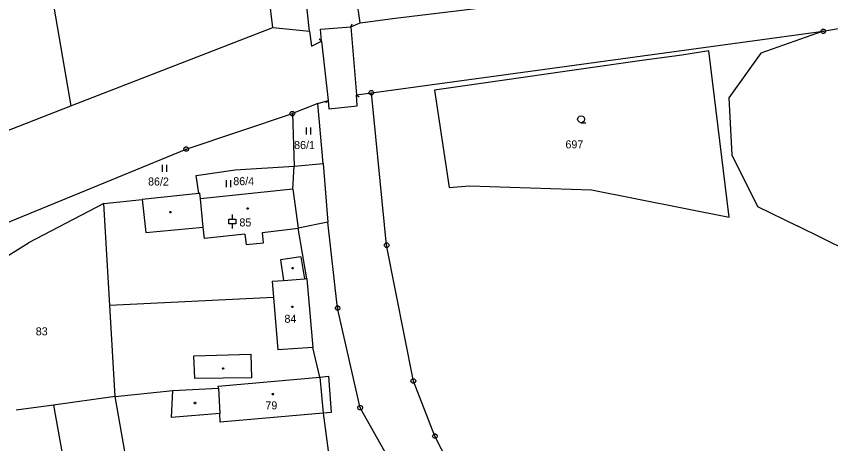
# Model space of a CAD drawing. Extents: x -812394 to -807601, y -1013098 to -1009266.
# Drawn here: x -809780.5 to -809607.5, y -1010903.9 to -1010813 of the extents above; entities that cross this region are included whole.
import ezdxf

# ---------------------------------------------------------------- set-up
doc = ezdxf.new("R2010")
doc.units = 0
for name, color, linetype in [('KN_HRANICE', 7, 'Continuous'), ('KN_KULTURY', 7, 'Continuous'), ('KN_MEZNIKY', 7, 'Continuous'), ('KN_PARCELY', 7, 'Continuous'), ('KN_SLUCKY', 7, 'Continuous')]:
    doc.layers.add(name, color=color, linetype=linetype)

# ---------------------------------------------------------------- blocks, each defined once
blk = doc.blocks.new('304')
blk.add_lwpolyline([(0, 0), (-0.38, 0.1), (-0.65, 0.37), (-0.75, 0.74), (-0.65, 1.11), (-0.38, 1.38), (-0.01, 1.48), (0.36, 1.38), (0.63, 1.11), (0.73, 0.73), (0.63, 0.35), (0.36, 0.08), (-0.02, -0.02), (0.98, -0.02)])
blk = doc.blocks.new('306')
for p, q in [((-0.5, 1.5), (-0.5, 0)), ((0.5, 0), (0.5, 1.5))]:
    blk.add_line(p, q)
blk = doc.blocks.new('318')
blk.add_line((0, 2), (0, 3))
blk.add_lwpolyline([(0, 0), (0, 1), (-0.75, 1), (-0.75, 2), (0, 2), (0.75, 2), (0.75, 1), (0, 1)])
blk = doc.blocks.new('402')
blk.add_lwpolyline([(0.09, 0.15), (0.18, 0), (0.09, -0.15), (-0.09, -0.15), (-0.18, 0), (-0.09, 0.15), (0.09, 0.15)])
blk = doc.blocks.new('105')
blk.add_line((-0.12, 0), (0.12, 0))
blk.add_lwpolyline([(0.15, 0.48), (0.4, 0.3), (0.5, 0.01), (0.4, -0.28), (0.15, -0.46), (-0.16, -0.46), (-0.41, -0.28), (-0.51, 0.01), (-0.41, 0.3), (-0.16, 0.48), (0.15, 0.48)])
blk = doc.blocks.new('4201')
blk.add_line((0, 0), (-0.5, -0.5))

msp = doc.modelspace()

# ---------------------------------------------------------------- linework, layer by layer
at = {"layer": 'KN_HRANICE'}
for p, q in [((-809776.12, -1010790.59), (-809768.91, -1010832.11)), ((-809718.25, -1010816.21), (-809720.85, -1010791.69)), ((-809707.49, -1010814.44), (-809710.32, -1010793.53)), ((-809726.02, -1010815.44), (-809727.35, -1010804.19)), ((-809700.6, -1010813.52), (-809643.49, -1010806.47)), ((-809609.07, -1010816.23), (-809583.77, -1010811.56)), ((-809709.48, -1010815.3), (-809707.49, -1010814.44)), ((-809707.49, -1010814.44), (-809701.59, -1010813.65)), ((-809701.59, -1010813.65), (-809700.6, -1010813.52)), ((-809768.91, -1010832.11), (-809726.02, -1010815.44)), ((-809726.02, -1010815.44), (-809718.25, -1010816.21)), ((-809718.25, -1010816.21), (-809717.84, -1010819.37)), ((-809715.88, -1010815.78), (-809709.48, -1010815.3)), ((-809715.65, -1010818.36), (-809715.88, -1010815.78)), ((-809705.08, -1010829.3), (-809609.07, -1010816.23)), ((-809717.84, -1010819.37), (-809715.65, -1010818.36)), ((-809708.23, -1010829.73), (-809705.08, -1010829.3)), ((-809708.1, -1010832.05), (-809708.23, -1010829.73)), ((-809701.84, -1010861.69), (-809705.08, -1010829.3)), ((-809795, -1010842.25), (-809768.91, -1010832.11)), ((-809716.45, -1010831.55), (-809721.87, -1010833.74)), ((-809716.45, -1010831.55), (-809714.29, -1010830.95)), ((-809715.34, -1010844.3), (-809716.45, -1010831.55)), ((-809714.29, -1010830.95), (-809714.1, -1010832.7)), ((-809714.1, -1010832.7), (-809708.1, -1010832.05)), ((-809744.44, -1010841.28), (-809721.87, -1010833.74)), ((-809721.87, -1010833.74), (-809721.48, -1010844.89)), ((-809788.59, -1010859.35), (-809744.44, -1010841.28)), ((-809721.48, -1010844.89), (-809715.34, -1010844.3)), ((-809715.34, -1010844.3), (-809714.35, -1010856.77)), ((-809742.28, -1010846.91), (-809734.04, -1010845.7)), ((-809734.04, -1010845.7), (-809721.48, -1010844.89)), ((-809721.76, -1010849.8), (-809721.48, -1010844.89)), ((-809741.74, -1010850.68), (-809742.28, -1010846.91)), ((-809741.74, -1010850.68), (-809753.76, -1010851.95)), ((-809741.55, -1010850.66), (-809741.74, -1010850.68)), ((-809741.42, -1010851.87), (-809741.55, -1010850.66)), ((-809721.76, -1010849.8), (-809741.42, -1010851.87)), ((-809761.95, -1010852.82), (-809777.96, -1010861.22)), ((-809761.95, -1010852.82), (-809753.76, -1010851.95)), ((-809760.65, -1010874.53), (-809761.95, -1010852.82)), ((-809714.35, -1010856.77), (-809720.67, -1010858.1)), ((-809718.78, -1010868.81), (-809720.67, -1010858.1)), ((-809712.26, -1010875.07), (-809714.35, -1010856.77)), ((-809791.19, -1010869.46), (-809777.96, -1010861.22)), ((-809696.17, -1010890.56), (-809701.84, -1010861.69)), ((-809726.19, -1010869.35), (-809723.78, -1010869.17)), ((-809726.19, -1010869.35), (-809725.89, -1010872.83)), ((-809723.78, -1010869.17), (-809719.27, -1010868.85)), ((-809718.78, -1010868.81), (-809719.27, -1010868.85)), ((-809718.78, -1010868.81), (-809717.54, -1010883.42)), ((-809725.89, -1010872.83), (-809760.65, -1010874.53)), ((-809759.51, -1010893.83), (-809760.65, -1010874.53)), ((-809707.45, -1010896.24), (-809712.26, -1010875.07)), ((-809716.06, -1010889.76), (-809717.54, -1010883.42)), ((-809737.62, -1010891.67), (-809716.06, -1010889.76)), ((-809716.06, -1010889.76), (-809714.21, -1010889.51)), ((-809714.21, -1010889.51), (-809713.65, -1010897.28)), ((-809691.58, -1010902.27), (-809696.17, -1010890.56)), ((-809759.51, -1010893.83), (-809747.26, -1010892.56)), ((-809747.26, -1010892.56), (-809737.6, -1010892.07)), ((-809737.6, -1010892.07), (-809737.62, -1010891.67)), ((-809759.51, -1010893.83), (-809772.62, -1010895.72)), ((-809754.39, -1010922.74), (-809759.51, -1010893.83)), ((-809772.62, -1010895.72), (-809780.58, -1010896.79)), ((-809772.62, -1010895.72), (-809767.28, -1010925.14)), ((-809713.65, -1010897.28), (-809715.33, -1010897.38)), ((-809715.33, -1010897.38), (-809714.24, -1010905.37)), ((-809688.11, -1010930.67), (-809707.45, -1010896.24)), ((-809685.82, -1010913.52), (-809691.58, -1010902.27))]:
    msp.add_line(p, q, dxfattribs=at)
for points in [[(-809609.07, -1010816.23), (-809622.36, -1010820.88), (-809629.15, -1010830.35), (-809628.52, -1010842.52), (-809623.05, -1010853.45), (-809614.59, -1010857.61)], [(-809521.17, -1010864.79), (-809541.42, -1010869.76), (-809562.13, -1010870.38), (-809583.78, -1010865.98), (-809603.73, -1010862.94), (-809614.59, -1010857.61)]]:
    msp.add_lwpolyline(points, dxfattribs=at)
msp.add_lwpolyline([(-809691.7, -1010828.74), (-809688.53, -1010849.4), (-809684.21, -1010849.11), (-809658.29, -1010849.93), (-809629.1, -1010855.77), (-809633.37, -1010820.41), (-809639.13, -1010821.28), (-809648.14, -1010822.51)], close=True, dxfattribs=at)
at = {"layer": 'KN_SLUCKY'}
for p, q in [((-809709.48, -1010815.3), (-809708.23, -1010829.73)), ((-809715.65, -1010818.36), (-809714.29, -1010830.95)), ((-809721.76, -1010849.8), (-809720.67, -1010858.1)), ((-809753.76, -1010851.95), (-809753.04, -1010859)), ((-809740.79, -1010857.85), (-809741.42, -1010851.87)), ((-809753.04, -1010859), (-809740.79, -1010857.85)), ((-809740.55, -1010860.29), (-809740.79, -1010857.85)), ((-809728.23, -1010858.97), (-809720.67, -1010858.1)), ((-809731.95, -1010859.34), (-809740.55, -1010860.29)), ((-809731.95, -1010859.34), (-809731.7, -1010861.58)), ((-809728.04, -1010861.21), (-809728.23, -1010858.97)), ((-809731.7, -1010861.58), (-809728.04, -1010861.21)), ((-809720.09, -1010864.16), (-809724.37, -1010864.8)), ((-809724.37, -1010864.8), (-809723.78, -1010869.17)), ((-809720.09, -1010864.16), (-809719.27, -1010868.85)), ((-809725.89, -1010872.83), (-809724.95, -1010883.96)), ((-809717.54, -1010883.42), (-809724.95, -1010883.96)), ((-809742.8, -1010885.24), (-809730.68, -1010884.82)), ((-809742.56, -1010890.05), (-809742.8, -1010885.24)), ((-809730.68, -1010884.82), (-809730.54, -1010889.91)), ((-809730.54, -1010889.91), (-809742.56, -1010890.05)), ((-809716.06, -1010889.76), (-809715.33, -1010897.38)), ((-809747.53, -1010898.29), (-809747.26, -1010892.56)), ((-809737.6, -1010892.07), (-809737.3, -1010897.44)), ((-809737.3, -1010897.44), (-809747.53, -1010898.29)), ((-809737.2, -1010899.28), (-809737.3, -1010897.44)), ((-809715.33, -1010897.38), (-809737.2, -1010899.28))]:
    msp.add_line(p, q, dxfattribs=at)

# ---------------------------------------------------------------- block references
at = {"layer": 'KN_KULTURY'}
for name, p in [('304', (-809660.52, -1010835.66)), ('306', (-809718.42, -1010838.2)), ('306', (-809749.07, -1010846.12)), ('306', (-809735.43, -1010849.36)), ('402', (-809747.77, -1010854.66)), ('402', (-809731.38, -1010853.87)), ('318', (-809734.6, -1010858.16)), ('402', (-809721.84, -1010866.6)), ('402', (-809721.89, -1010874.78)), ('402', (-809736.58, -1010887.9)), ('402', (-809726.02, -1010893.37)), ('402', (-809742.55, -1010895.24))]:
    msp.add_blockref(name, p, dxfattribs=at)
at = {"layer": 'KN_MEZNIKY'}
for p in [(-809609.07, -1010816.23), (-809705.08, -1010829.3), (-809721.87, -1010833.74), (-809744.44, -1010841.28), (-809701.84, -1010861.69), (-809712.26, -1010875.07), (-809696.17, -1010890.56), (-809707.45, -1010896.24), (-809691.58, -1010902.27)]:
    msp.add_blockref('105', p, dxfattribs=at)
at = {"layer": 'KN_SLUCKY'}
for p, rotation in [((-809709.48, -1010815.3), -162.55874399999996), ((-809715.65, -1010818.36), -88.016935), ((-809708.23, -1010829.73), 99.465473)]:
    msp.add_blockref('4201', p, dxfattribs=dict(at, rotation=rotation))
msp.add_blockref('4201', (-809714.29, -1010830.95), dxfattribs=at)

# ---------------------------------------------------------------- texts
at = {"layer": 'KN_PARCELY'}
for s, p in [('86/1', (-809721.5, -1010841.26)), ('697', (-809663.85, -1010841.12)), ('86/2', (-809752.53, -1010849.01)), ('86/4', (-809734.43, -1010848.94)), ('85', (-809733.12, -1010857.71)), ('84', (-809723.55, -1010878.18)), ('83', (-809776.39, -1010880.85)), ('79', (-809727.6, -1010896.58))]:
    msp.add_text(s, height=1.7, dxfattribs=at).set_placement(p)

doc.saveas('drawing.dxf')
